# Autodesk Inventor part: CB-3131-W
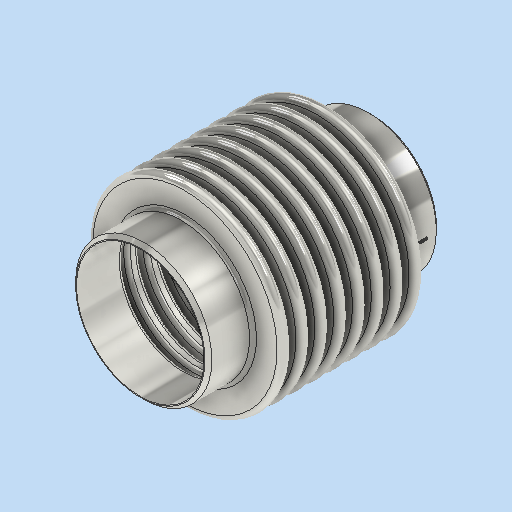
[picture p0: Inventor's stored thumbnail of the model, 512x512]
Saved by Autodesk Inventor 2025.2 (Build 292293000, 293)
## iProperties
Company: DN.RU
Created: 2026-04
Part Number: CB-3131-W
Material: Типовые
Document SubType Name: Modeling
Designer: DN.RU
Density: 3.61177 g/cm^3
Appearance: По умолчанию
Description: D140-02126
Mass: 3800 g
Surface Area: 8808.78 cm^2
Volume: 1052.12 cm^3
Author: DN.RU
Title: Компенсатор сильфонный осевой DN.ru Ду150 Ру16
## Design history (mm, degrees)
sketch "Эскиз1"
  geometry: L1 (0, 0)-(0, -135); L2 (79.5, -135)-(79.5, 0); L3 (79.5, 0)-(0, 0); L4 (79.5, 0)-(79.5, -11); L5 (51.5, -11)-(107.5, -11); L6 (51.5, -17)-(107.5, -17); L7 (107.5, -5)-(51.5, -5); L8 (107.5, -15)-(51.5, -15); L9 (51.5, -7)-(107.5, -7); L10 (107.5, -27)-(51.5, -27); L11 (51.5, -29)-(107.5, -29); L12 (51.5, -33)-(107.5, -33); L13 (51.5, -39)-(107.5, -39); L14 (107.5, -37)-(51.5, -37); L15 (107.5, -49)-(51.5, -49); L16 (51.5, -51)-(107.5, -51); L17 (51.5, -55)-(107.5, -55); L18 (51.5, -61)-(107.5, -61); L19 (107.5, -59)-(51.5, -59); L20 (107.5, -71)-(51.5, -71); L21 (51.5, -73)-(107.5, -73); L22 (51.5, -77)-(107.5, -77); L23 (51.5, -83)-(107.5, -83); L24 (107.5, -81)-(51.5, -81); L25 (0, -135)-(79.5, -135); L26 (79.5, -135)-(74.5, -135); L27 (79.5, -71)-(77.5, -71); L28 (74.5, -135)-(74.5, -81); L29 (79.5, -73)-(77.5, -73); L30 (77.5, -73)-(77.5, -59); L31 (79.5, -51)-(77.5, -51); L32 (77.5, -51)-(77.5, -37); L33 (79.5, -29)-(77.5, -29); L34 (77.5, -29)-(77.5, -15); L35 (79.5, -7)-(77.5, -7); L36 (77.5, -7)-(77.5, 0); A1 r 6 centre (51.5, -11) between (51.5, -5) and (51.5, -17); A2 r 6 centre (107.5, -11) between (107.5, -17) and (107.5, -5); A3 r 4 centre (51.5, -11) between (51.5, -7) and (51.5, -15); A4 r 4 centre (107.5, -11) between (107.5, -15) and (107.5, -7); A5 r 4 centre (51.5, -33) between (51.5, -29) and (51.5, -37); A6 r 6 centre (51.5, -33) between (51.5, -27) and (51.5, -39); A7 r 4 centre (107.5, -33) between (107.5, -37) and (107.5, -29); A8 r 6 centre (107.5, -33) between (107.5, -39) and (107.5, -27); A9 r 4 centre (51.5, -55) between (51.5, -51) and (51.5, -59); A10 r 6 centre (51.5, -55) between (51.5, -49) and (51.5, -61); A11 r 4 centre (107.5, -55) between (107.5, -59) and (107.5, -51); A12 r 6 centre (107.5, -55) between (107.5, -61) and (107.5, -49); A13 r 4 centre (51.5, -77) between (51.5, -73) and (51.5, -81); A14 r 6 centre (51.5, -77) between (51.5, -71) and (51.5, -83); A15 r 4 centre (107.5, -77) between (107.5, -81) and (107.5, -73); A16 r 6 centre (107.5, -77) between (107.5, -83) and (107.5, -71); 18 further points
  constraints: 80 end point, 32 point on circle, 16 centre point, 15 point on line, 6 midpoint, 5 perpendicular, 4 tangent, 3 parallel, 2 vertical, 1 horizontal, 69 other
  dimensions: "d0" = 135 distance of L1.start L1.end; "d1" = 79.5 distance of L2.start L1.end; "d3" = 11 distance of L2.end L4.end; "d4" = 28 distance of L4.end L5.end; "d5" = 12 diameter of A2; "d6" = 2 distance between parallel lines of L6 L8; "d9" = 22 distance of L4.end point (79.5, -33); "d14" = 5 distance of L2.start L26.end; "d15" = 2 distance of L27.start L27.end; "d16" = 2 distance of L29.start L29.end; "d17" = 2 distance of L31.start L31.end; "d18" = 2 distance of L33.start L33.end; "d19" = 2 distance of L35.start L35.end
revolve "Вращение1" sketch "Эскиз1" stored, may be unused: angle "d20" = 360 deg
mirror "Зеркальное отражение1"
chamfer "Фаска1" distance "d21" = 4; stored, may be unused: second distance "d22" = 2, angle "d23" = 45 deg
fillet "Сопряжение1" dims "d24" = 4
node "РабПлоскость1"
sketch "Эскиз2"
  geometry: L1 (4.893, 15.322)-(4.893, -12.74); L2 (4.893, -12.74)-(-3.237, -12.74); L3 (-3.237, -12.74)-(-3.237, 15.322); L4 (-3.237, 15.322)-(4.893, 15.322); 1 further point
  constraints: 2 other
feature "Рельеф1" sketch "Эскиз2" dims "d25" = 0.1, "d26" = 0
node "Твердое тело1"
node "Эскиз — прямоугольный массив1" dims "d9" = 22, "d12" = 10
